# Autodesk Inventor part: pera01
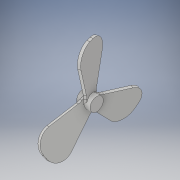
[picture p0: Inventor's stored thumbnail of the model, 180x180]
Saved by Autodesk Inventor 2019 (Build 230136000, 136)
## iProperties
Created: 2020-08
Part Number: pera01
Material: 一般
Document SubType Name: Modeling
Designer: kikut
Density: 1 g/cm^3
Appearance: 既定
Author: kikut
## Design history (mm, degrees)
sketch "スケッチ3"
  geometry: L1 (0.005, -0.009)-(-0.001, 0.01); L2 (-0.001, 0.01)-(-0.005, 0.009); L3 (-0.005, 0.009)-(0.001, -0.01); L4 (0.001, -0.01)-(0.005, -0.009); L5 (0.005, -0.009)-(-0.005, 0.009); L6 (-0.001, 0.01)-(0.001, -0.01); L7 (0, -0.014)-(0, 0.014) reference; 3 further points
  constraints: 12 end point, 3 midpoint, 2 parallel, 1 coincident, 1 perpendicular
  dimensions: "d8" = 0.02 distance of L1.start L1.end; "d9" = 15 deg angle of L7 L1; "d19" = 0.004 distance of L3.end L1.start
extrude "押し出し1" new body sketch "スケッチ3" distance "d10" = 0.079; taper "d11" = 0 deg
sketch "スケッチ6"
  geometry: L1 (-0.02, 0)-(-0.02, 0.079) reference; L2 (-0.02, 0.01)-(-0.04, 0.079); L3 (-0.04, 0.079)-(0.02, 0.079); L4 (0.02, 0.079)-(0, 0.01); L5 (0, 0)-(0, 0.079) reference; L6 (-0.02, 0.01)-(0, 0.01); L7 (-0.02, 0)-(0, 0) reference; 1 further point
  constraints: 8 end point, 2 perpendicular, 2 point on line
  dimensions: "d20" = 0.06 distance of L2.end L3.end; "d21" = 0.01 distance between parallel lines of L7 L6; "d22" = 0.02 distance from line of L1 L2.end
extrude "押し出し3" join sketch "スケッチ6" distance "d23" = 0.004; taper "d24" = 0 deg
fillet "フィレット2" dims "d25" = 0.02
fillet "フィレット3" dims "d26" = 0.02
pattern_circular "円形状パターン2" dims "d28" = 360 deg
sketch "スケッチ7"
  geometry: L1 (-0.008, -0.005)-(0, 0) reference; C1 r 0.01 at (0, 0)
  constraints: 1 centre point, 1 coincident
  dimensions: "d30" = 0.02 diameter of C1
extrude "押し出し4" join sketch "スケッチ7" stored distance "d31" = 0.02; taper "d32" = 0 deg
node "ソリッド1"
